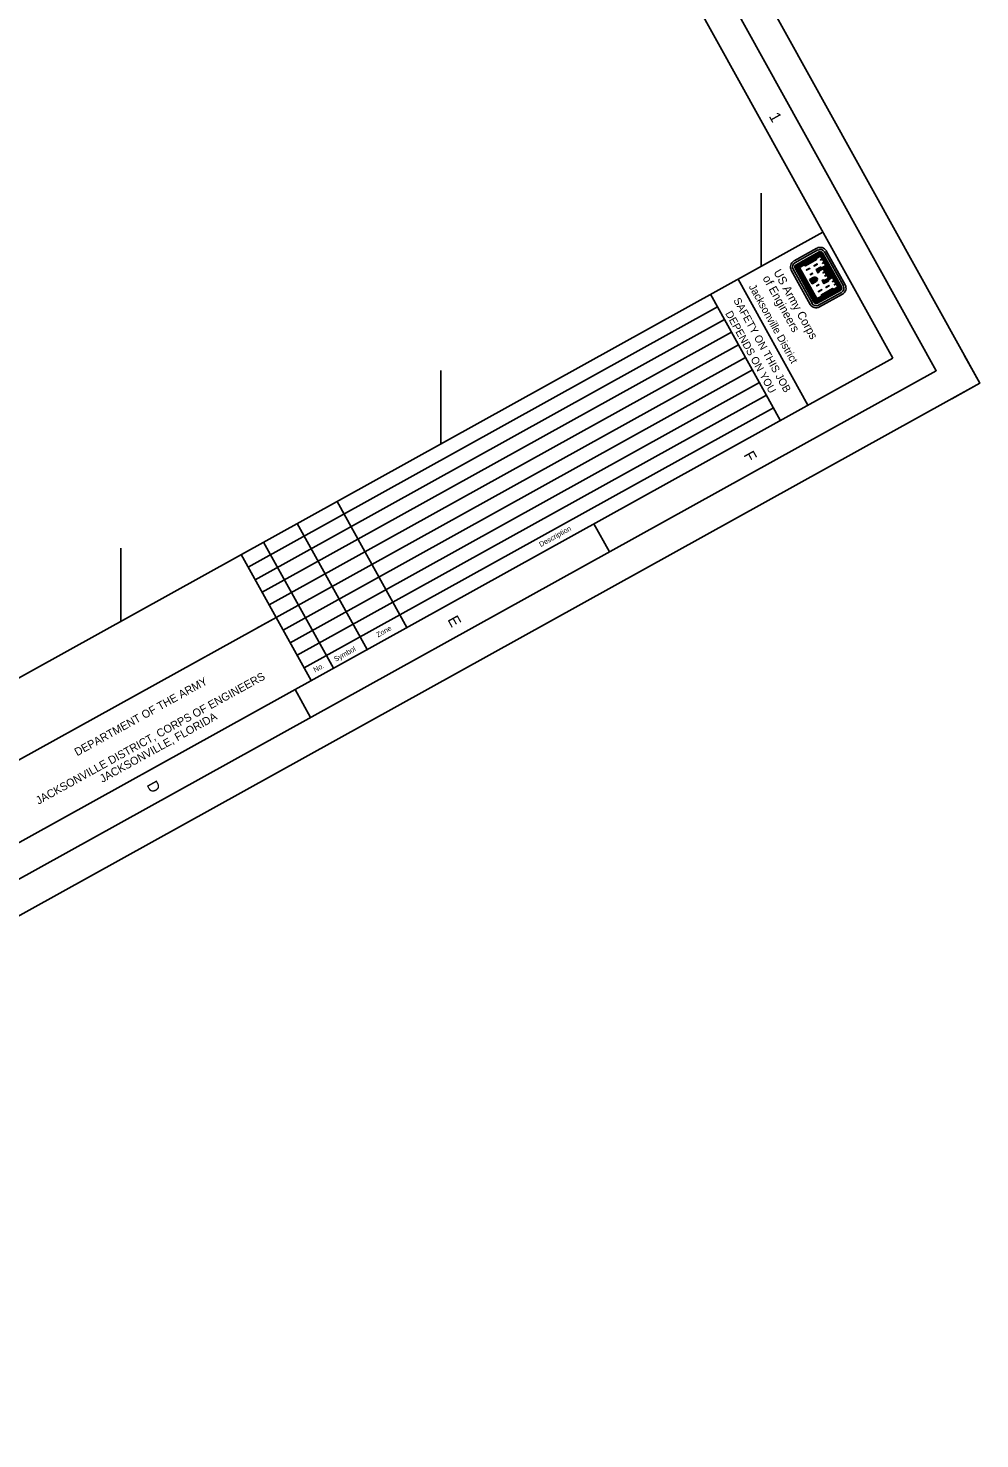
# Model space of a CAD drawing. Extents: x 601234 to 606341, y 798155 to 803651.
# Drawn here: x 604856 to 606341, y 798155 to 800358 of the extents above; entities that cross this region are included whole.
import ezdxf

# ---------------------------------------------------------------- set-up
doc = ezdxf.new("R2010")
doc.units = 0
for name, color, linetype in [('G-ANNO-NPLT', 7, 'Continuous'), ('G-ANNO-TEXT-LOGO', 7, 'Continuous'), ('G-ANNO-TEXT-TTLB', 7, 'Continuous'), ('G-ANNO-TTLB', 7, 'Continuous'), ('V-TOPO-COOR-STAT', 7, 'Continuous')]:
    doc.layers.add(name, color=color, linetype=linetype)

msp = doc.modelspace()

# ---------------------------------------------------------------- linework, layer by layer
at = {"layer": 'G-ANNO-NPLT'}
msp.add_lwpolyline([(604207.8, 803651.4), (606341.2, 799803.3), (603367.7, 798154.7), (601234.2, 802002.9)], close=True, dxfattribs=at)
msp.add_lwpolyline([(606297.5, 799779), (606341.2, 799803.3), (606317, 799847)], dxfattribs=at)
at = {"layer": 'G-ANNO-TEXT-LOGO'}
for p, q in [((606087, 800014.1), (606051.2, 799994.2)), ((606052.7, 799991.4), (606088.6, 800011.3)), ((606090.3, 800008.2), (606054.4, 799988.3)), ((606090.7, 800007.4), (606054.9, 799987.6)), ((606091.1, 800006.7), (606055.3, 799986.9)), ((606091.5, 800006), (606055.7, 799986.1)), ((606092, 800005.2), (606056.1, 799985.3)), ((606092.4, 800004.4), (606056.8, 799984.6)), ((606092.8, 800003.7), (606058, 799984.4)), ((606085.5, 799998.8), (606067.2, 799988.7)), ((606122.2, 799951.8), (606092.8, 800005)), ((606123, 799952.3), (606093.5, 800005.5)), ((606123.7, 799952.7), (606094.2, 800005.8)), ((606124.5, 799953.1), (606095, 800006.3)), ((606125.3, 799953.5), (606095.8, 800006.7)), ((606098.8, 800008.4), (606128.3, 799955.2)), ((606131.1, 799956.7), (606101.6, 800009.9)), ((606046.9, 799979.6), (606076.4, 799926.4)), ((606079.3, 799928), (606049.8, 799981.2)), ((606082.3, 799929.7), (606052.9, 799982.9)), ((606083, 799930.1), (606053.6, 799983.3)), ((606083.8, 799930.6), (606054.4, 799983.7)), ((606084.6, 799931), (606055.1, 799984.2)), ((606085.3, 799931.4), (606055.8, 799984.6)), ((606085.9, 799932.2), (606056.8, 799984.6)), ((606086.3, 799933.3), (606058, 799984.4)), ((606085.2, 799997.6), (606068.5, 799988.4)), ((606097.7, 799983.7), (606106.8, 799967.4)), ((606098.5, 799984.1), (606107.5, 799967.8)), ((606099.2, 799984.5), (606108.2, 799968.2)), ((606100, 799984.9), (606109, 799968.6)), ((606100.8, 799985.4), (606109.8, 799969.1)), ((606101.5, 799985.7), (606110.5, 799969.5)), ((606102.3, 799986.2), (606111.3, 799969.9)), ((606075.4, 799965.2), (606081.2, 799968.4)), ((606075.4, 799965.2), (606079.3, 799958.2)), ((606075.8, 799964.5), (606081.6, 799967.7)), ((606076.2, 799963.7), (606082.1, 799967)), ((606076.6, 799962.9), (606082.5, 799966.2)), ((606077, 799962.2), (606082.9, 799965.5)), ((606077.6, 799961.2), (606083.5, 799964.4)), ((606078, 799960.5), (606083.9, 799963.7)), ((606078.4, 799959.7), (606084.3, 799962.9)), ((606078.9, 799958.9), (606084.7, 799962.2)), ((606079.3, 799958.2), (606085.1, 799961.5)), ((606121.5, 799951.9), (606085.9, 799932.2)), ((606121.9, 799951.1), (606086.1, 799931.2)), ((606121.1, 799952.6), (606086.3, 799933.3)), ((606122.4, 799950.3), (606086.5, 799930.4)), ((606122.8, 799949.6), (606086.9, 799929.7)), ((606123.2, 799948.8), (606087.4, 799929)), ((606123.6, 799948.1), (606087.8, 799928.2)), ((606125.3, 799945.1), (606089.4, 799925.2)), ((606091, 799922.3), (606126.9, 799942.2)), ((606113.1, 799948.9), (606094.9, 799938.9)), ((606112, 799949.3), (606095.2, 799940.1))]:
    msp.add_line(p, q, dxfattribs=at)
for points in [[(606093.1, 800003.1), (606086.2, 799999.2), (606085.6, 799996.9), (606068.9, 799987.7), (606066.5, 799988.3), (606058.9, 799984.1), (606086.5, 799934.2), (606094.1, 799938.4), (606094.8, 799940.9), (606111.5, 799950.1), (606113.9, 799949.4), (606120.8, 799953.2), (606117.1, 799959.8), (606114.3, 799964.8), (606111.7, 799969.6), (606104.8, 799965.7), (606104.2, 799963.3), (606098.1, 799959.9), (606096.1, 799963.5), (606096.7, 799963.9), (606099.1, 799963.2), (606106, 799967), (606102.3, 799973.5), (606099.5, 799978.6), (606096.9, 799983.2), (606090.1, 799979.4), (606089.4, 799977), (606088.8, 799976.6), (606086.8, 799980.3), (606092.9, 799983.7), (606095.3, 799983), (606102.2, 799986.8), (606098.5, 799993.4), (606095.7, 799998.4), (606093.1, 800003.1)], [(606092.7, 800001.9), (606087, 799998.7), (606086.3, 799996.3), (606069, 799986.7), (606066.5, 799987.4), (606060, 799983.8), (606086.9, 799935.3), (606093.4, 799938.9), (606094, 799941.5), (606111.3, 799951.1), (606113.8, 799950.3), (606119.6, 799953.5), (606117, 799958.2), (606114.3, 799956.7), (606114, 799957.1), (606116.7, 799958.6), (606114.2, 799963.3), (606111.5, 799961.8), (606111.3, 799962.1), (606114, 799963.6), (606111.4, 799968.3), (606105.6, 799965.1), (606104.9, 799962.7), (606097.8, 799958.8), (606095, 799963.8), (606096.7, 799964.8), (606099.1, 799964.1), (606104.9, 799967.3), (606102.3, 799972), (606099.5, 799970.5), (606099.4, 799970.8), (606102.1, 799972.3), (606099.4, 799977.1), (606096.7, 799975.6), (606096.5, 799976), (606099.2, 799977.5), (606096.6, 799982.1), (606090.9, 799978.9), (606090.2, 799976.5), (606088.5, 799975.6), (606085.7, 799980.6), (606092.8, 799984.6), (606095.2, 799983.9), (606101, 799987.1), (606098.4, 799991.7), (606095.7, 799990.2), (606095.5, 799990.6), (606098.2, 799992.1), (606095.6, 799996.9), (606092.8, 799995.4), (606092.7, 799995.7), (606095.4, 799997.2), (606092.7, 800001.9)], [(606075.7, 799983.1), (606070.6, 799980.3), (606070.9, 799979.7), (606076, 799982.6), (606075.7, 799983.1)], [(606087.4, 799989.6), (606082.3, 799986.8), (606082.6, 799986.2), (606087.7, 799989), (606087.4, 799989.6)], [(606093.7, 799982.5), (606093, 799982.7), (606088, 799980), (606088.9, 799978.3), (606089.4, 799980.1), (606093.8, 799982.5)], [(606080.2, 799975.1), (606076.6, 799973.1), (606076.9, 799972.6), (606080.4, 799974.6), (606080.2, 799975.1)], [(606090.2, 799957.1), (606086.6, 799955.1), (606086.4, 799955.5), (606089.9, 799957.5), (606090.2, 799957.1)], [(606103.7, 799964.5), (606103.5, 799963.8), (606098.5, 799961.1), (606097.6, 799962.7), (606099.3, 799962.2), (606103.7, 799964.7)], [(606106.2, 799955.5), (606101.2, 799952.7), (606100.9, 799953.2), (606106, 799956), (606106.2, 799955.5)], [(606094.6, 799949.1), (606089.4, 799946.2), (606089.2, 799946.7), (606094.4, 799949.5), (606094.6, 799949.1)]]:
    msp.add_lwpolyline(points, dxfattribs=at)
for centre, major_axis, start_param, end_param in [((606092.3, 800004.7), (5.19, -9.37), 1.57078, 3.141576), ((606092.3, 800004.7), (3.63, -6.55), 1.57078, 3.141576), ((606092.3, 800004.7), (1.95, -3.51), 1.57078, 3.141576), ((606092.3, 800004.7), (1.53, -2.75), 1.57078, 3.141576), ((606092.3, 800004.7), (1.11, -2), 1.57078, 3.141576), ((606092.3, 800004.7), (0.69, -1.24), 1.57078, 3.141576), ((606092.3, 800004.7), (0.265, -0.477), 1.57078, 3.141576), ((606056.3, 799984.8), (-5.19, 9.37), 6.28317, 7.853966), ((606056.3, 799984.8), (-3.63, 6.55), 6.28317, 7.853966), ((606056.3, 799984.8), (-1.95, 3.51), 6.28317, 7.853966), ((606056.3, 799984.8), (-1.53, 2.75), 6.28317, 7.853966), ((606056.3, 799984.8), (-1.11, 2), 6.28317, 7.853966), ((606056.3, 799984.8), (-0.69, 1.24), 6.28317, 7.853966), ((606056.3, 799984.8), (-0.265, 0.477), 6.28317, 7.853966), ((606083.5, 799963.4), (-2.69, 4.86), 4.985832, 6.214359), ((606083.5, 799963.4), (-2.27, 4.1), 4.947465, 6.21436), ((606083.5, 799963.4), (-1.85, 3.34), 4.947465, 6.21436), ((606083.5, 799963.4), (-1.43, 2.58), 4.947465, 6.21436), ((606083.5, 799963.4), (-1.01, 1.82), 4.947465, 6.214359), ((606082.1, 799966.1), (1.01, -1.82), 0.068794, 1.335689), ((606082.1, 799966.1), (1.43, -2.58), 0.068794, 1.335689), ((606082.1, 799966.1), (1.85, -3.34), 0.068795, 1.335689), ((606082.1, 799966.1), (2.27, -4.1), 0.068795, 1.335689), ((606082.1, 799966.1), (2.69, -4.86), 0.068795, 1.29842), ((606121.7, 799951.6), (3.63, -6.55), 6.28317, 7.853966), ((606121.7, 799951.6), (5.19, -9.37), 6.283169, 7.853965), ((606121.7, 799951.6), (0.265, -0.477), 6.283169, 7.853965), ((606121.7, 799951.6), (0.69, -1.24), 6.283169, 7.853965), ((606121.7, 799951.6), (1.11, -2), 6.283169, 7.853965), ((606121.7, 799951.6), (1.53, -2.75), 6.283169, 7.853965), ((606121.7, 799951.6), (1.95, -3.51), 6.283169, 7.853965), ((606085.8, 799931.7), (5.19, -9.37), 4.712373, 6.28317), ((606085.8, 799931.7), (-3.63, 6.55), 1.570781, 3.141577), ((606085.8, 799931.7), (1.95, -3.51), 4.712373, 6.28317), ((606085.8, 799931.7), (1.53, -2.75), 4.712373, 6.28317), ((606085.8, 799931.7), (1.11, -2), 4.712373, 6.28317), ((606085.8, 799931.7), (0.69, -1.24), 4.712373, 6.28317), ((606085.8, 799931.7), (0.265, -0.477), 4.712373, 6.28317)]:
    msp.add_ellipse(centre, major_axis=major_axis, ratio=0.99964, start_param=start_param, end_param=end_param, dxfattribs=at)
at = {"layer": 'G-ANNO-TTLB'}
for p, q in [((606096.2, 800039), (603297.5, 798487.5)), ((605963.9, 799965.7), (606073, 799768.9)), ((605920.7, 799942.4), (606029.8, 799745.6)), ((605931.8, 799922.4), (605199, 799516.1)), ((605942.7, 799902.7), (605209.9, 799496.4)), ((605953.6, 799883), (605220.8, 799476.7)), ((605964.5, 799863.3), (605231.7, 799457)), ((605975.4, 799843.6), (605242.6, 799437.4)), ((605986.3, 799824), (605253.5, 799417.7)), ((605997.2, 799804.3), (605264.4, 799398)), ((606008.1, 799784.6), (605275.3, 799378.3)), ((606019.1, 799764.9), (605286.2, 799358.6)), ((605337.7, 799618.5), (605446.8, 799421.7)), ((605275.5, 799584), (605384.6, 799387.2)), ((605762.9, 799539.8), (605738.7, 799583.5)), ((605188.1, 799535.6), (605297.2, 799338.8)), ((605223, 799554.9), (605332, 799358.1)), ((604490.6, 799021), (605242.7, 799437.2)), ((605242.7, 799437.2), (605211.7, 799420)), ((605296.5, 799281.2), (605272.3, 799325))]:
    msp.add_line(p, q, dxfattribs=at)
for points in [[(601302.2, 801983.4), (603387.1, 798222.7), (606273.3, 799822.7), (604188.3, 803583.4)], [(606205.3, 799842.2), (604205.2, 803449.9), (601406.6, 801898.3), (603406.6, 798290.7)]]:
    msp.add_lwpolyline(points, close=True, dxfattribs=at)
at = {"layer": 'V-TOPO-COOR-STAT'}
for p, q in [((606000, 799985.7), (606000, 800100.1)), ((605500, 799708.5), (605500, 799822.9)), ((605000, 799431.3), (605000, 799545.7))]:
    msp.add_line(p, q, dxfattribs=at)

# ---------------------------------------------------------------- texts
at = {"layer": 'G-ANNO-TEXT-TTLB'}
for s, height, rotation, p in [('US Army Corps', 13.086, 299.0039, (606018.7, 799976.7)), ('Jacksonville District', 11.9, 299.0039, (605980.1, 799954.1)), ('of Engineers', 13.086, 299.0039, (606001.7, 799967.3)), ('SAFETY ON THIS JOB', 11.9, 299.0039, (605956.1, 799932.7)), ('DEPENDS ON YOU', 11.9, 299.0039, (605943.5, 799912.2)), ('Description', 8, 29.0039, (605655.9, 799547.2)), ('Zone', 8, 29.0039, (605401.8, 799406)), ('Symbol', 8, 29.0039, (605335.6, 799368)), ('No.', 8, 29.0039, (605303.5, 799351.3)), ('JACKSONVILLE DISTRICT, CORPS OF ENGINEERS', 12.5, 29.0039, (604871.7, 799144.8)), ('DEPARTMENT OF THE ARMY', 12.5, 29.0039, (604932, 799220.5)), ('JACKSONVILLE, FLORIDA', 12.5, 29.0039, (604971.5, 799179))]:
    msp.add_text(s, height=height, rotation=rotation, dxfattribs=at).set_placement(p)
at = {"layer": 'G-ANNO-TTLB'}
for s, p in [('1', (606011.5, 800220.3)), ('F', (605971.8, 799691.3)), ('E', (605509.7, 799434.2)), ('D', (605039.8, 799176.2))]:
    msp.add_text(s, height=17.5, rotation=299.0039, dxfattribs=at).set_placement(p)

doc.saveas('drawing.dxf')
